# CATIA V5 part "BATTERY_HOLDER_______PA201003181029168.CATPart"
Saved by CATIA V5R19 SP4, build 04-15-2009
Part number: BATTERY_HOLDER_______PA201003181029168
Bounding box of the stored display mesh (mm): x -13 to 13, y -8 to 8, z -29 to 29
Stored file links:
  E:\CadInnWork\InWork\BATTERY_HOLDER_______PA201003181029168.CATPart
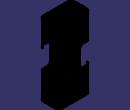
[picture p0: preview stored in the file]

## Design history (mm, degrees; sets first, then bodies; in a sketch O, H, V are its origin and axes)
Parameters
  Update = false
  PDM_version = "A"
  PDM_iteration = 1
  PDM_owner = "moren                    "
  PDM_comment = ""
  PDM_partnumber = "PA002170EA6A57201003181029160008"
Body1 (main body)
  Sketch1 on xy-plane, origin (0, 0, 0), H (1, 0, 0), V (0, 1, 0)
    line L1 (13, 8) -> (13, -8)
    line L2 (13, -8) -> (-13, -8)
    line L3 (-13, -8) -> (-13, 8)
    line L4 (-13, 8) -> (13, 8)
    length L4 = 26
    length L1 = 16
    vertical: L1 V, L3 V
    horizontal: L2 H, L4 H
    equidistance: L1 L3 O, L2 L4 O
  Pad1: profile Sketch1, direction (0, 0, 1), length 29, mirrored extent
  Fillet1: radius 3, on edge [face of Pad1 from Sketch1.L4 | face of Pad1 from Sketch1.L1]; edge [face of Pad1 from Sketch1.L3 | face of Pad1 from Sketch1.L4]; edge [face of Pad1 from Sketch1.L1 | face of Pad1 from Sketch1.L2]; edge [face of Pad1 from Sketch1.L2 | face of Pad1 from Sketch1.L3]
  Sketch2 on xy-plane, origin (0, 0, 0), H (1, 0, 0), V (0, 1, 0)
    line L1 (0.75, 7.25) -> (0.75, -7.25)
    line L2 (0.75, -7.25) -> (10, -7.25)
    line L3 (0.75, 7.25) -> (10, 7.25)
    arc A1 centre (10, 5) radius 2.25 from (10, 7.25) to (12.25, 5) cw
    point P5 (10, 5)
    arc A2 centre (10, -5) radius 2.25 from (10, -7.25) to (12.25, -5) ccw
    reference projected arc E1 centre (10, -5) radius 3 from (10, -8) to (13, -5) ccw from edge [end face of Pad1 | face of Fillet1]
    reference projected arc E2 centre (10, 5) radius 3 from (13, 5) to (10, 8) ccw from edge [end face of Pad1 | face of Fillet1]
    reference intersected line E3 through (0, 0) direction (0, 1) from yz-plane
    reference projected line E4 (13, 8) -> (-13, 8) from edge [face of Pad1 from Sketch1.L4 | end face of Pad1]
    reference projected line E5 (-13, -8) -> (13, -8) from edge [face of Pad1 from Sketch1.L2 | end face of Pad1]
    line L4 (12.25, 5) -> (15.1189, 5)
    line L5 (12.25, -5) -> (15.1189, -5)
    line L6 (15.1189, 5) -> (15.1189, -5)
    reference intersected line E6 through (0, 0) direction (-1, 0) from zx-plane
    distance L1 E3 = 0.75
    distance L3 E4 = 0.75
    distance L2 E5 = 0.75
    vertical: L1 V, L6 V
    horizontal: L2 H, L3 H, L4 H, L5 H
    tangency: A1 L3, A2 L2
    concentricity: E1 A2, A1 E2
    coincidence: L4 P5
    symmetry: L5 L4 E6
  Pocket1: profile Sketch2, direction (0, 0, -1), length 28, mirrored extent
  Mirror1: of Pocket1, about yz-plane
  Sketch3 on zx-plane, origin (0, 0, 0), H (-1, 0, 0), V (0, 0, 1)
    line L1 (7.5, 8) -> (18.3621, 8)
    line L2 (18.3621, 8) -> (18.3621, -8)
    line L3 (18.3621, -8) -> (7.5, -8)
    line L4 (4.5, -5) -> (4.5, 5)
    reference intersected line E1 through (0, 0) direction (-1, 0) from xy-plane
    reference intersected line E2 through (0, 0) direction (0, -1) from yz-plane
    arc A1 centre (7.5, 5) radius 3 from (7.5, 8) to (4.5, 5) ccw
    arc A2 centre (7.5, -5) radius 3 from (4.5, -5) to (7.5, -8) ccw
    distance L4 E2 = 4.5
    length L2 = 16
    radius A1 = 3
    radius A2 = 3
    horizontal: L1 H, L3 H
    vertical: L2 V, L4 V
    symmetry: L3 L1 E1
    tangency: A1 L1, A1 L4, A2 L4, A2 L3
  Pocket2: profile Sketch3, direction (0, -1, 0), through (limit type 3), opposite side through (limit type 3)
  Mirror2: of Pocket2, about yz-plane
  Sketch4 on zx-plane, origin (0, 0, 0), H (-1, 0, 0), V (0, 0, 1)
    line L1 (11.5, 28) -> (16.9342, 28)
    line L2 (16.9342, 28) -> (16.9342, 26)
    line L3 (16.9342, 26) -> (11.5, 26)
    line L4 (11, 26.5) -> (11, 27.5)
    reference intersected line E1 (0.75, 28) -> (15.1189, 28) from face of Mirror1
    reference intersected line E2 through (0, 0) direction (0, -1) from yz-plane
    arc A1 centre (11.5, 27.5) radius 0.5 from (11.5, 28) to (11, 27.5) ccw
    arc A2 centre (11.5, 26.5) radius 0.5 from (11, 26.5) to (11.5, 26) ccw
    distance L4 E2 = 11
    length L2 = 2
    radius A1 = 0.5
    radius A2 = 0.5
    horizontal: L1 H, L3 H
    vertical: L2 V, L4 V
    coincidence: L1 E1
    tangency: A1 L1, A1 L4, A2 L4, A2 L3
  Pocket3: profile Sketch4, direction (0, -1, 0), through (limit type 3), opposite side through (limit type 3)
  Mirror3: of Pocket3, about yz-plane
  Sketch5, origin (0, 0, 0), H (-1, 0, 0), V (0, 0, -1)
    line L1 (11.5, 28) -> (16.9342, 28)
    line L2 (16.9342, 28) -> (16.9342, 26)
    line L3 (16.9342, 26) -> (11.5, 26)
    line L4 (11, 26.5) -> (11, 27.5)
    arc A1 centre (11.5, 27.5) radius 0.5 from (11.5, 28) to (11, 27.5) ccw
    arc A2 centre (11.5, 26.5) radius 0.5 from (11, 26.5) to (11.5, 26) ccw
    length L2 = 2
    radius A1 = 0.5
    radius A2 = 0.5
    horizontal: L1 H, L3 H
    vertical: L2 V, L4 V
    tangency: A1 L1, A1 L4, A2 L4, A2 L3
  Pocket4: profile Sketch5, direction (0, -1, 0), through (limit type 3), opposite side through (limit type 3)
  Mirror4: of Pocket4, about yz-plane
